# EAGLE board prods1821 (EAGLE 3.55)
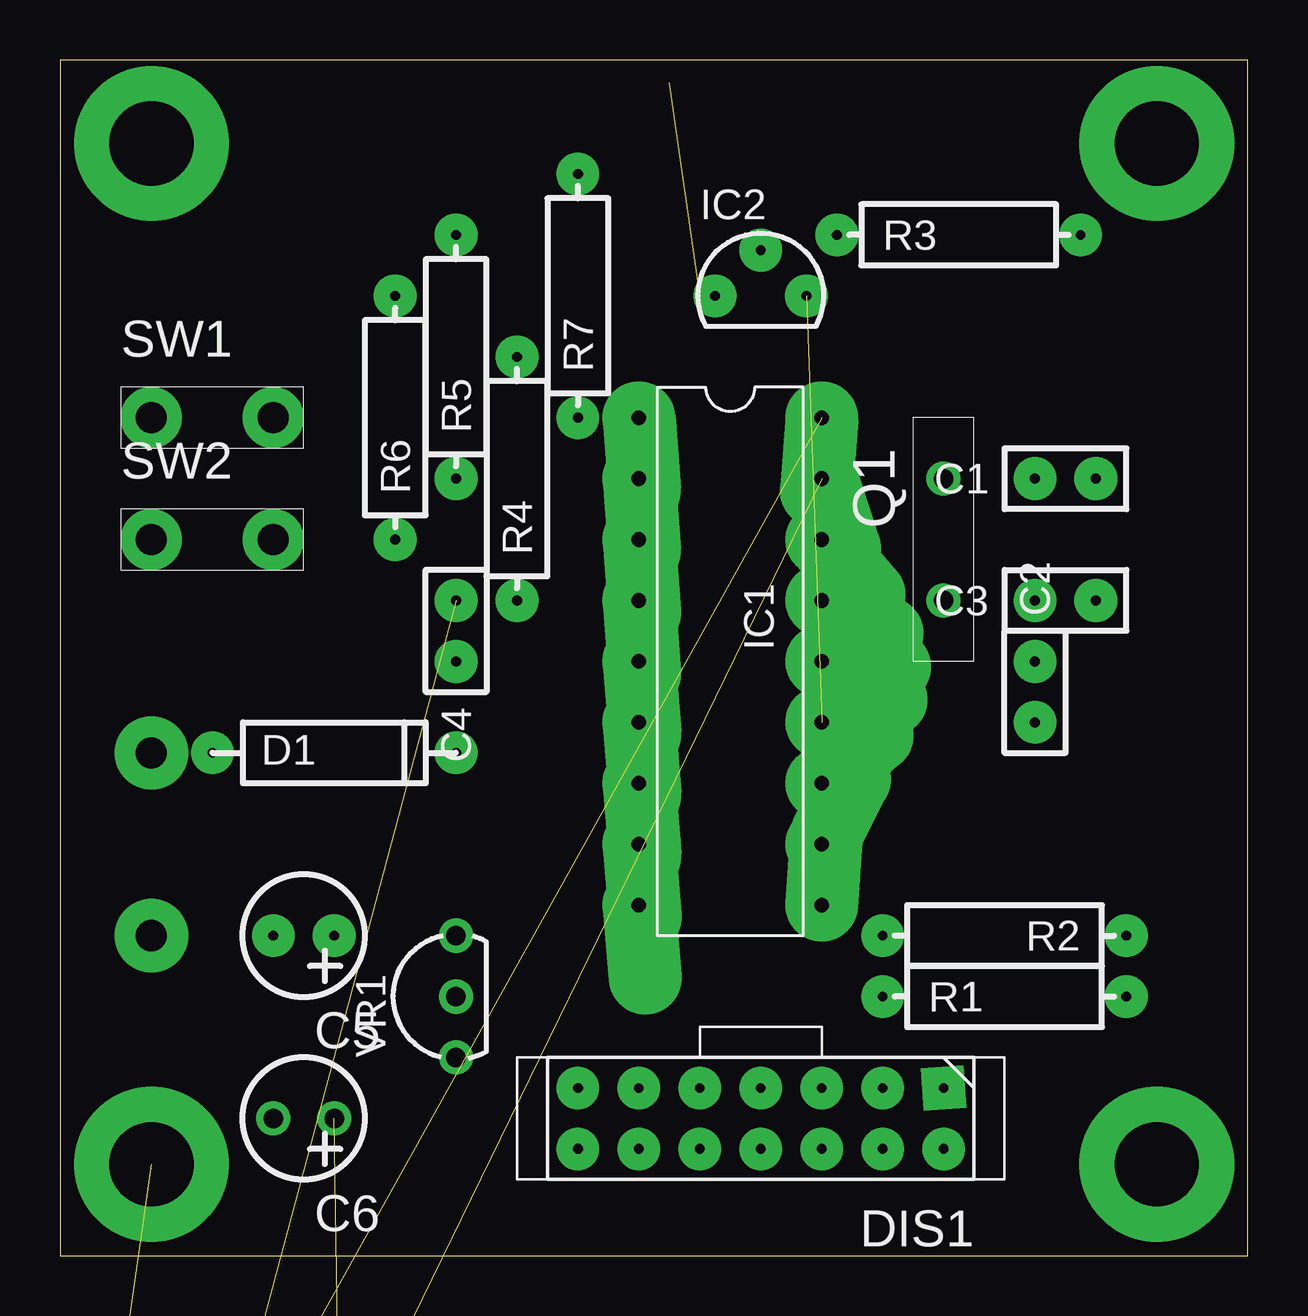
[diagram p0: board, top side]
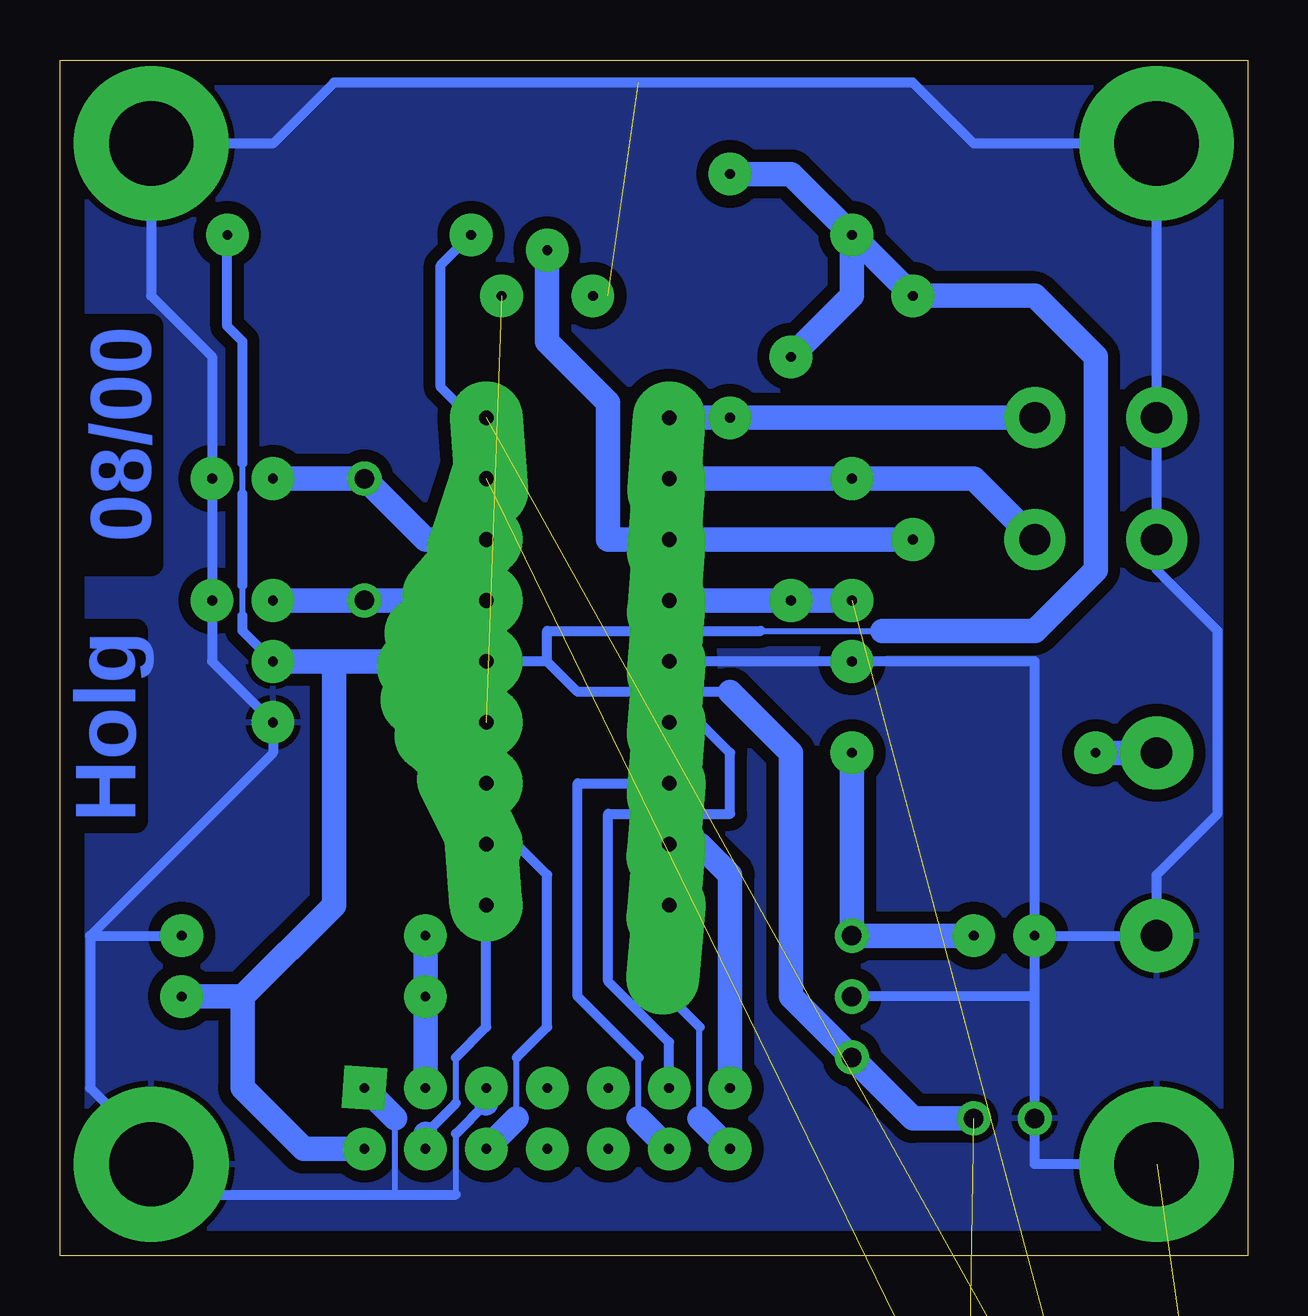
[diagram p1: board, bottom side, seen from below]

Size 49.52 x 49.84 mm. Coordinates in mm from the lower left corner, seen from the top.
Outline: 0,0 49.52,0 49.52,49.84 0,49.84 0,0
Copper layers used: Bottom

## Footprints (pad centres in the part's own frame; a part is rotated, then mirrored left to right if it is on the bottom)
RM2,5 = drill 0.406 pad 1.778 round:  0,0;  2.54,0
KO01 = drill 0.406 pad 1.778 round:  0,0;  2.54,0
KO01' = drill 0.813 pad 1.422 round:  0,0;  2.54,0
O04 = drill 0.406 pad 1.778 round:  0,0;  10.16,0
7 = drill 0.406 pad 1.778 square:  0,0 | drill 0.406 pad 1.778 round:  2.54,0;  5.08,0;  7.62,0;  10.16,0;  10.16,2.54;  7.62,2.54;  5.08,2.54;  2.54,2.54;  0,2.54;  12.7,0;  12.7,2.54;  15.24,0;  15.24,2.54
L-18B = drill 0.61 pad 3.048 offset:  0,0;  2.54,0;  15.24,0;  17.78,0;  5.08,0;  7.62,0;  12.7,0;  10.16,0;  20.32,0;  20.32,7.62;  17.78,7.62;  15.24,7.62;  12.7,7.62;  10.16,7.62;  7.62,7.62;  5.08,7.62;  2.54,7.62;  0,7.62
92 = drill 0.406 pad 1.778 round:  -0.635,0;  1.27,1.905;  3.175,0
GEL = drill 1.295 pad 3.048 round:  0,0
ARZ_ST = drill 0.813 pad 1.422 round:  0,0;  5.08,0
S04 = drill 0.406 pad 1.778 round:  0,0;  10.16,0
H-1POL = drill 1.295 pad 2.54 round:  0,0;  5.08,0
HRUNG = drill 3.505 pad 6.452 round:  0,0
92-B = drill 0.813 pad 1.422 round:  -2.54,0;  2.54,0;  0,0

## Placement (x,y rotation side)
C1  27p  [RM2,5]  43.18,32.39 180 top
C2  100n  [RM2,5]  40.64,22.22 90 top
C3  27p  [RM2,5]  43.18,27.3 180 top
C4  100n  [RM2,5]  16.51,27.3 270 top
C5  100u  [KO01]  11.43,13.34 180 top
C6  47u  [KO01']  11.43,5.71 180 top
D1  1N4148  [O04]  6.35,20.95 0 top
DIS1  LCD  [7]  36.83,6.99 180 top
IC1  16F84P  [L-18B]  24.13,34.93 270 top
IC2  DS1821  [92]  27.94,40.01 0 top
N1  +  [GEL]  3.81,20.95 0 top
N2  -  [GEL]  3.81,13.34 0 top
Q1  4MHz  [ARZ_ST]  36.83,32.39 270 top
R1  12k  [S04]  34.29,10.79 0 top
R2  1k  [S04]  44.45,13.34 180 top
R3  10k  [S04]  32.39,42.55 0 top
R4  10k  [S04]  19.05,27.3 90 top
R5  10k  [S04]  16.51,32.39 90 top
R6  4k7  [S04]  13.97,29.84 90 top
R7  10k  [S04]  21.59,34.93 90 top
R8  10k  [S04]  not placed on the board
SW1  Right  [H-1POL]  3.81,34.93 0 top
SW2  Enter  [H-1POL]  3.81,29.84 0 top
SW3  Up  [H-1POL]  not placed on the board
SW4  Down  [H-1POL]  not placed on the board
SW5  Reset  [H-1POL]  not placed on the board
U$15  BOHRUNG  [HRUNG]  3.81,3.81 0 top
U$16  BOHRUNG  [HRUNG]  3.81,46.36 0 top
U$26  BOHRUNG  [HRUNG]  45.72,3.81 0 top
U$27  BOHRUNG  [HRUNG]  45.72,46.36 0 top
VR1  78L05  [92-B]  16.51,10.79 90 top

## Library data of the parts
C1-C5 D1 DIS1 IC2 R3 R5 R7 R8 = holg_plt
C6 N1 N2 R1 R2 R4 R6 U$15 U$16 U$26 U$27 VR1 = holgnorm
IC1 = PIC
Q1 = bts
SW1-SW5 = taster

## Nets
+5V: C2. C6. DIS1. IC1. R1. R3. R4. R5. R6. R7. R8. VR1.
+UB: C5. D1. VR1.
GND: C1. C2. C3. C4. C5. C6. DIS1. IC1. IC2. N2. R2. SW1. SW2. SW3. SW4. SW5. U$15. U$16. U$26. U$27. VR1.
N$1: C1. IC1. Q1.
N$2: D1. N1.
N$3: C3. IC1. Q1.
N$4: IC1. R3. SW3.
N$5: C4. IC1. R4. SW5.
N$6: IC1. R8. SW4.
N$7: IC1. IC2.
N$9: IC1. R5. SW2.
N$10: IC1. IC2. R6.
N$11: DIS1. IC1.
N$12: DIS1. IC1.
N$13: DIS1. IC1.
N$14: DIS1. IC1.
N$15: IC1. R7. SW1.
N$22: DIS1. R1. R2.
N$23: DIS1. IC1.
N$24: DIS1. IC1.

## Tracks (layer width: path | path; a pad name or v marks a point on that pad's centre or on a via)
+5V  (1 unrouted)
  Bottom 0.254: 20.32,26.04 15.24,26.04 | 41.91,31.75 41.91,33.02 | 41.91,26.67 41.91,27.94
  Bottom 0.406: 29.21,24.76 31.75,24.76 | 29.21,24.76 29.21,26.04 20.32,26.04 | 21.59,23.49 27.94,23.49 29.21,24.76 | R3. 42.55,38.73 41.91,38.1 41.91,33.02 | 41.91,27.94 41.91,31.75 | C2. 41.91,26.04 41.91,26.67
  Bottom 1.016: 31.75,24.76 38.1,24.76 | 38.1,24.76 C2. | 41.91,10.79 R1. | 41.91,10.79 38.1,14.61 38.1,24.76 | 15.24,26.04 8.89,26.04 6.35,28.57 6.35,37.47 8.89,40.01 R6. R5. | R5. 19.05,45.09 R7. | R5. 16.51,40.01 R4. | 41.91,10.79 41.91,6.99 39.37,4.45 36.83,4.45 | 11.43,5.71 13.97,5.71 16.51,8.26 19.05,10.79 19.05,20.95 21.59,23.49
+UB
  Bottom 1.016: 11.43,13.34 16.51,13.34 D1.
GND  (4 unrouted)
  Bottom 0.254: 35.56,2.54 35.56,5.71 | 33.02,2.54 33.02,5.08
  Bottom 0.406: 24.13,24.76 C4. 8.89,24.76 C5. | 26.67,40.01 27.3,40.01 | 48.26,13.34 48.26,6.99 45.72,4.45 U$26. 44.45,2.54 35.56,2.54 33.02,2.54 | 48.26,13.34 44.45,13.34 | 48.26,13.34 40.64,20.95 40.64,22.22 43.18,24.76 43.18,27.3 43.18,32.39 43.18,37.47 45.72,40.01 U$27. 40.64,46.36 38.1,48.9 25.4,48.9 13.97,48.9 11.43,46.36 U$16. 3.81,34.93 3.81,29.84 3.81,28.57 1.27,26.04 1.27,18.41 3.81,15.88 N2. C5. | 8.89,10.79 C5. | 8.89,10.79 C6. 8.89,3.81 U$15. | 8.89,10.79 VR1. | 33.02,5.08 31.75,6.35
  Bottom 1.016: 35.56,5.71 36.83,6.99 | 31.75,6.35 31.75,6.99
  pour Bottom (isolate 0.508): 0.64,48.9 0.64,0.64 48.9,0.64 48.9,48.9
N$1
  Bottom 1.016: C1. 36.83,32.39 34.29,29.84 31.75,29.84
N$2
  Bottom 1.016: N1. 6.35,20.95
N$3
  Bottom 1.016: 31.75,27.3 Q1. C3.
N$4  (1 unrouted)
  Bottom 0.406: 32.39,42.55 33.66,41.27 33.66,36.2 32.39,34.93 IC1.
N$5  (1 unrouted)
  Bottom 1.016: 24.13,27.3 19.05,27.3 16.51,27.3
N$6  (2 unrouted)
N$7  (1 unrouted)
N$9
  Bottom 1.016: 24.13,32.39 16.51,32.39 11.43,32.39 SW2.
N$10
  Bottom 1.016: 13.97,29.84 24.13,29.84 26.67,29.84 26.67,35.56 29.21,38.1 29.21,41.91
N$11
  Bottom 0.406: 24.13,22.22 22.86,22.22 21.59,20.95 21.59,18.41 26.67,18.41 26.67,11.43 24.13,8.89 24.13,6.99
N$12
  Bottom 0.254: 25.4,5.71 25.4,8.26
  Bottom 0.406: 24.13,19.68 27.94,19.68 27.94,10.79 25.4,8.26
  Bottom 1.016: 24.13,4.45 25.4,5.71
N$13
  Bottom 1.016: 24.13,17.14 22.86,17.14 21.59,15.88 21.59,6.99
N$14
  Bottom 0.254: 22.86,5.71 22.86,9.53
  Bottom 0.406: 24.13,14.61 24.13,10.79 22.86,9.53
  Bottom 1.016: DIS1. 22.86,5.71
N$15
  Bottom 1.016: SW1. 21.59,34.93 24.13,34.93
N$22
  Bottom 1.016: R2. 34.29,10.79 34.29,6.99
N$23
  Bottom 0.254: 33.02,6.35 33.02,8.26
  Bottom 0.406: 31.75,14.61 31.75,9.53 33.02,8.26 | 34.29,5.08 33.02,6.35
  Bottom 1.016: 34.29,4.45 34.29,5.08
N$24
  Bottom 0.254: 30.48,5.71 30.48,8.26
  Bottom 0.406: 31.75,17.14 30.48,17.14 29.21,15.88 29.21,9.53 30.48,8.26
  Bottom 1.016: 31.75,4.45 30.48,5.71

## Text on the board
Bottom: 08/00 | Holg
